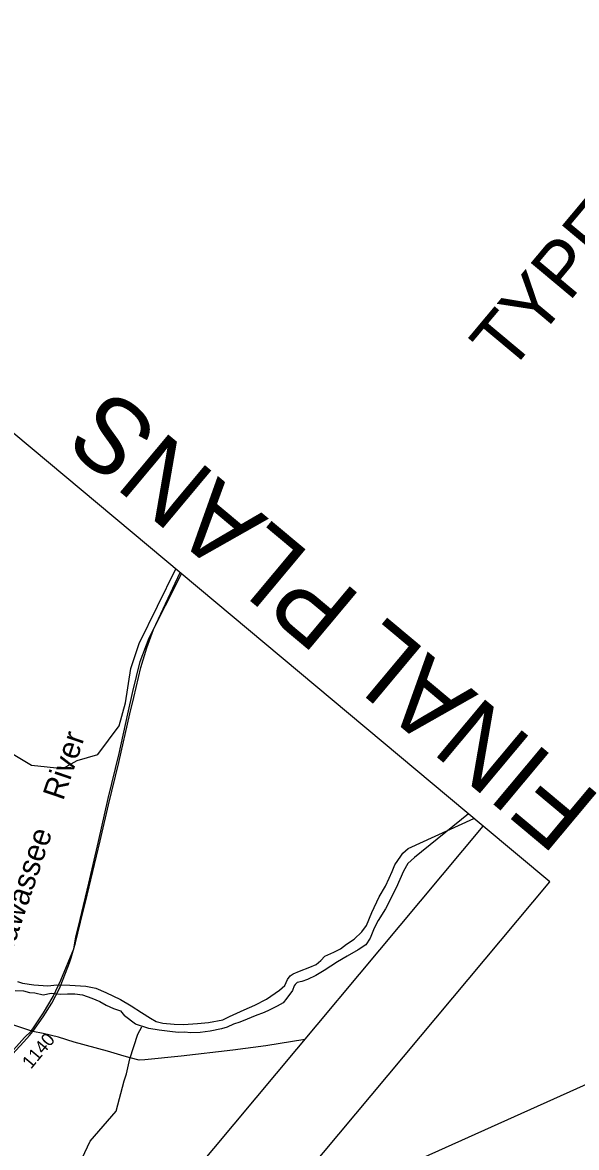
# Model space of a CAD drawing. Extents: x 555292 to 2368606, y 503623 to 1171444.
# Drawn here: x 2357615 to 2358242, y 1163265 to 1164538 of the extents above; entities that cross this region are included whole.
import ezdxf

# ---------------------------------------------------------------- set-up
doc = ezdxf.new("R2010")
doc.units = 0
for name, color, linetype in [('Exist Road Non-System Type 51 Label', 7, 'Continuous'), ('Old_Level_1', 7, 'Continuous'), ('Old_Level_28', 7, 'Continuous'), ('Old_Level_3', 7, 'Continuous'), ('Old_Level_32', 7, 'Continuous'), ('Old_Level_59', 7, 'Continuous'), ('Old_Level_60', 7, 'Continuous'), ('Old_Level_8', 7, 'Continuous'), ('Sheet Title CELL', 7, 'Continuous')]:
    doc.layers.add(name, color=color, linetype=linetype)

msp = doc.modelspace()

# ---------------------------------------------------------------- linework, layer by layer
at = {"layer": 'Old_Level_1'}
for p, q in [((2358136.3, 1163628.5), (2357074.9, 1164516.4)), ((2357068.1, 1162351.5), (2358136.3, 1163628.5)), ((2358211.7, 1163565.5), (2358136.3, 1163628.5)), ((2357143.5, 1162288.4), (2358211.7, 1163565.5))]:
    msp.add_line(p, q, dxfattribs=at)
at = {"layer": 'Old_Level_28'}
for points in [[(2357736.3, 1163755.5), (2357740.8, 1163774.2), (2357748.9, 1163808.2), (2357755.6, 1163830.3), (2357763.4, 1163851.1), (2357793.3, 1163915.4)], [(2357668.1, 1163473.9), (2357669.9, 1163479.6), (2357674.8, 1163496.5), (2357680.5, 1163519.8), (2357686.1, 1163542.6), (2357702.7, 1163612.1), (2357712.3, 1163652.6), (2357723.9, 1163700.6), (2357736.3, 1163755.5)], [(2357656.8, 1163445.1), (2357658.5, 1163448.6), (2357668.1, 1163473.9)], [(2357626.5, 1163396.3), (2357638.4, 1163412.8), (2357648, 1163428.4), (2357656.8, 1163445.1)], [(2357588.5, 1163354), (2357607.6, 1163374.6), (2357616.5, 1163384.4), (2357622.9, 1163391.6), (2357626.5, 1163396.3)]]:
    msp.add_lwpolyline(points, dxfattribs=at)
at = {"layer": 'Old_Level_3'}
for points in [[(2357734, 1163755.8), (2357739.7, 1163780.9), (2357748.2, 1163814.9), (2357758.5, 1163841.7), (2357795, 1163914)], [(2357673.2, 1163489.7), (2357675.3, 1163503), (2357680.3, 1163523), (2357690, 1163564.1), (2357700.9, 1163611.3), (2357712, 1163659.8), (2357724.2, 1163710.9), (2357734, 1163755.8)], [(2357628.1, 1163401.6), (2357638.9, 1163417.5), (2357649.6, 1163435.9), (2357658.3, 1163454.2), (2357673.2, 1163489.7)], [(2357570.3, 1163340.6), (2357591.1, 1163360.5), (2357608.3, 1163379.4), (2357617.3, 1163389.3), (2357624.6, 1163396.8), (2357628.1, 1163401.6)]]:
    msp.add_lwpolyline(points, dxfattribs=at)
at = {"layer": 'Old_Level_32'}
msp.add_line((2357747, 1163364), (2357736.8, 1163366.3), dxfattribs=at)
for points in [[(2357626.5, 1163396.3), (2357578.5, 1163412.2)], [(2357736.8, 1163366.3), (2357730, 1163368.2), (2357711, 1163373.9), (2357673.3, 1163384.3), (2357655.7, 1163389.7), (2357638.2, 1163394.1), (2357626.5, 1163396.3)], [(2357934.5, 1163387.3), (2357890.4, 1163380), (2357853.1, 1163375.2), (2357794.7, 1163368.5), (2357753.3, 1163364.4), (2357747, 1163364)]]:
    msp.add_lwpolyline(points, dxfattribs=at)
at = {"layer": 'Old_Level_59'}
for points in [[(2357600.5, 1163712.3), (2357625.1, 1163697.4), (2357660.8, 1163694), (2357676.9, 1163702.9), (2357700.2, 1163709.7), (2357724.3, 1163741.9), (2357731.5, 1163768.1), (2357737.4, 1163806.8), (2357747.1, 1163835.4), (2357788.4, 1163919.6)], [(2357438.4, 1162794.2), (2357544, 1162977.9), (2357563.6, 1163004), (2357625.7, 1163070.2), (2357635.3, 1163097.7), (2357643.8, 1163135.7), (2357649.7, 1163149.3), (2357653.1, 1163161.9), (2357652.5, 1163169), (2357653.3, 1163177.9), (2357666.9, 1163220.3), (2357691.4, 1163272.1), (2357721.1, 1163306), (2357729.9, 1163340.4), (2357732.6, 1163348.3), (2357736.3, 1163365.3), (2357745.6, 1163393.3), (2357750.1, 1163401.4)]]:
    msp.add_lwpolyline(points, dxfattribs=at)
at = {"layer": 'Old_Level_60'}
for points in [[(2358119.8, 1163642.4), (2358058.6, 1163593.3), (2358051.2, 1163586.2), (2358046.1, 1163577.8), (2358038, 1163558.9), (2358025.8, 1163535.1), (2358017.6, 1163521.7), (2358012.9, 1163513.1), (2358008.6, 1163501.9), (2358003.5, 1163494.2), (2357995, 1163488.6), (2357982.6, 1163481.5), (2357971.6, 1163474.9), (2357956.4, 1163465.3), (2357946.8, 1163459.8), (2357937.4, 1163455.1), (2357931.3, 1163452.9)], [(2357609.3, 1163453), (2357615, 1163451), (2357627.8, 1163449), (2357643.6, 1163448.1), (2357654, 1163448.9), (2357668.6, 1163448.8), (2357686.8, 1163447.6), (2357697.8, 1163445.2), (2357709.3, 1163440.5), (2357725.7, 1163432.4), (2357738.1, 1163425.4), (2357749.8, 1163417.8), (2357760, 1163411.2), (2357766.3, 1163407.6), (2357773.9, 1163405.7), (2357786.7, 1163404.7), (2357797.1, 1163404.2), (2357813, 1163405.5), (2357825.6, 1163406.4), (2357841.6, 1163409.4), (2357849.3, 1163413.4), (2357865.7, 1163420.7), (2357877.8, 1163426), (2357891, 1163432.9), (2357905.8, 1163443.1), (2357911.8, 1163448.4), (2357915, 1163455), (2357918, 1163459.3), (2357921.4, 1163461.6), (2357928.4, 1163464.7), (2357940, 1163469), (2357947.4, 1163472), (2357952.5, 1163476.6), (2357957.2, 1163481.4), (2357967.2, 1163486), (2357975, 1163489.8), (2357981.7, 1163495.2), (2357990.4, 1163500.6), (2357999.1, 1163509.1), (2358004.3, 1163516.3), (2358010.3, 1163531), (2358018.5, 1163548.5), (2358025.9, 1163560.6), (2358030, 1163569.8), (2358033.4, 1163577.2), (2358036.4, 1163585), (2358043.2, 1163594.6), (2358045.6, 1163598.2), (2358051.3, 1163603.3), (2358125.9, 1163637.2)], [(2357931.3, 1163452.9), (2357925.9, 1163451.6), (2357923.6, 1163449.6), (2357922.5, 1163447.9), (2357920.7, 1163442.8), (2357914.1, 1163434.1), (2357910.1, 1163428.7), (2357903.1, 1163425), (2357894.2, 1163420.4), (2357888.4, 1163417.7), (2357878.4, 1163413.9), (2357869.1, 1163410.2), (2357860.9, 1163406.8), (2357853.7, 1163404.7), (2357846.6, 1163401.3), (2357840.1, 1163399.3), (2357827.3, 1163396.7), (2357815.9, 1163395.1), (2357805.2, 1163394.9), (2357798.6, 1163395.6), (2357791.3, 1163395.2), (2357781.9, 1163396.4), (2357769.7, 1163397.7), (2357758, 1163399.7), (2357743, 1163404.6), (2357730.5, 1163414.1)], [(2357606.5, 1163442.8), (2357616.2, 1163442.2), (2357622.7, 1163440.3), (2357629, 1163439.9), (2357638.2, 1163437.8), (2357647.4, 1163439.8), (2357657.9, 1163438.6), (2357665.8, 1163438.7)], [(2357665.8, 1163438.7), (2357674.2, 1163438.9), (2357682.8, 1163437.9), (2357693.5, 1163434.1), (2357702.5, 1163430.3), (2357709.7, 1163425.9), (2357718, 1163422.3), (2357725.8, 1163419.6), (2357730.5, 1163414.1)]]:
    msp.add_lwpolyline(points, dxfattribs=at)
at = {"layer": 'Sheet Title CELL'}
msp.add_lwpolyline([(2359897.4, 1162918.3), (2358377.2, 1162235.6), (2357945, 1163198.1), (2359465.2, 1163880.8)], close=True, dxfattribs=at)

# ---------------------------------------------------------------- texts
at = {"layer": 'Exist Road Non-System Type 51 Label'}
msp.add_text('Hiawassee    River', height=25, rotation=71.2235, dxfattribs=at).set_placement((2357596.4, 1163466.7))
at = {"layer": 'Old_Level_8'}
msp.add_text('1140', height=14.76, rotation=50.0895, dxfattribs=at).set_placement((2357624.5, 1163353))
at = {"layer": 'Sheet Title CELL'}
for s, height, rotation, p in [('TYPE OF WORK:', 61.912, 50.0895, (2358165.5, 1164139.7)), ('FINAL PLANS', 85, 140.0895, (2358271.9, 1163660.2))]:
    msp.add_text(s, height=height, rotation=rotation, dxfattribs=at).set_placement(p)

doc.saveas('drawing.dxf')
